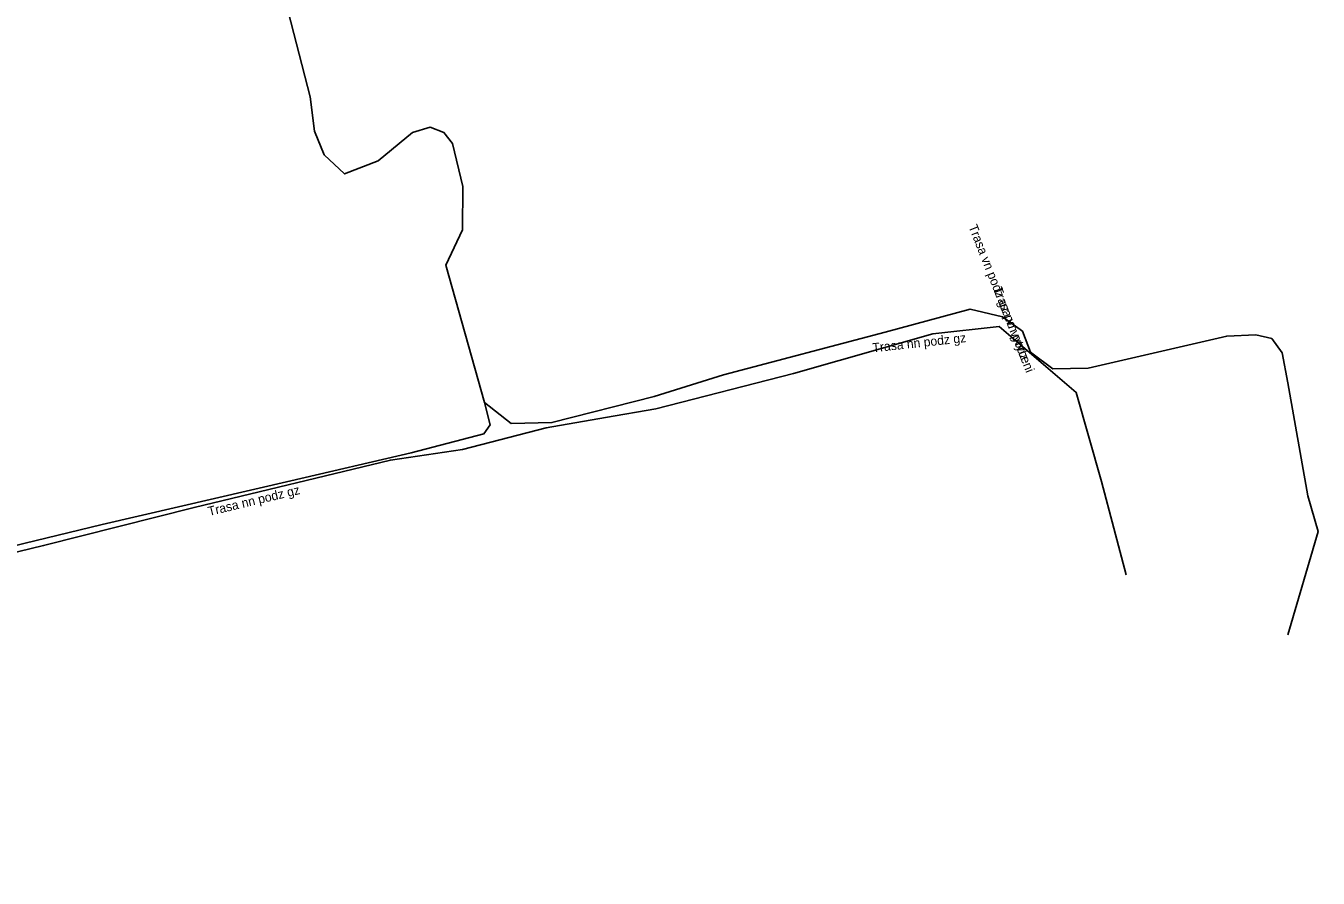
# Model space of a CAD drawing. Extents: x -473162 to -472629, y -1107202 to -1106680.
# Drawn here: x -472722.3 to -472651.3, y -1107100.6 to -1107053.9 of the extents above; entities that cross this region are included whole.
import ezdxf

# ---------------------------------------------------------------- set-up
doc = ezdxf.new("R2010")
doc.units = 0
for name, color, linetype in [('Popiskový text - Ostatní atributy Trasy', 7, 'Continuous'), ('Spojnice NN', 7, 'Continuous'), ('Spojnice VN', 7, 'Continuous')]:
    doc.layers.add(name, color=color, linetype=linetype)

msp = doc.modelspace()

# ---------------------------------------------------------------- linework, layer by layer
at = {"layer": 'Spojnice NN'}
for points in [[(-472661.88, -1107084), (-472663.22, -1107078.88), (-472664.62, -1107074), (-472668.85, -1107070.39), (-472672.48, -1107070.79), (-472680.13, -1107072.97), (-472687.68, -1107074.9), (-472690.449, -1107075.378)], [(-472690.449, -1107075.378), (-472693.7, -1107075.94), (-472698.29, -1107077.14), (-472702.25, -1107077.71), (-472713.02, -1107080.31), (-472721.28, -1107082.4), (-472726.565, -1107083.674)]]:
    msp.add_lwpolyline(points, dxfattribs=at)
at = {"layer": 'Spojnice VN'}
for points in [[(-472716.995, -1107015.385), (-472713.58, -1107028.195), (-472711.99, -1107034.185), (-472711.18, -1107037.515), (-472710.57, -1107041.2), (-472709.355, -1107047.29), (-472706.66, -1107057.79), (-472706.42, -1107059.68), (-472705.88, -1107060.975), (-472704.76, -1107062.02), (-472702.915, -1107061.3), (-472701.04, -1107059.755), (-472700.075, -1107059.45), (-472699.31, -1107059.75), (-472698.84, -1107060.35), (-472698.28, -1107062.705), (-472698.285, -1107065.095), (-472699.21, -1107067.025), (-472697.089, -1107074.548)], [(-472716.995, -1107015.385), (-472713.58, -1107028.195), (-472711.99, -1107034.185), (-472711.18, -1107037.515), (-472710.57, -1107041.2), (-472709.355, -1107047.29), (-472706.66, -1107057.79), (-472706.42, -1107059.68), (-472705.88, -1107060.975), (-472704.76, -1107062.02), (-472702.915, -1107061.3), (-472701.04, -1107059.755), (-472700.075, -1107059.45), (-472699.31, -1107059.75), (-472698.84, -1107060.35), (-472698.28, -1107062.705), (-472698.285, -1107065.095), (-472699.21, -1107067.025), (-472697.089, -1107074.548)], [(-472697.089, -1107074.548), (-472695.62, -1107075.7), (-472693.39, -1107075.66), (-472687.78, -1107074.22), (-472683.97, -1107073.04), (-472675.1, -1107070.7), (-472670.43, -1107069.44), (-472668.66, -1107069.85), (-472667.57, -1107070.65), (-472667.12, -1107071.79), (-472665.9, -1107072.71), (-472663.96, -1107072.67), (-472656.36, -1107070.91), (-472654.76, -1107070.84), (-472653.89, -1107071.05), (-472653.31, -1107071.84), (-472653.002, -1107073.475), (-472651.9, -1107079.67), (-472651.34, -1107081.63), (-472653.01, -1107087.293)], [(-472697.089, -1107074.548), (-472695.62, -1107075.7), (-472693.39, -1107075.66), (-472687.78, -1107074.22), (-472683.97, -1107073.04), (-472675.1, -1107070.7), (-472670.43, -1107069.44), (-472668.66, -1107069.85), (-472667.57, -1107070.65), (-472667.12, -1107071.79), (-472665.9, -1107072.71), (-472663.96, -1107072.67), (-472656.36, -1107070.91), (-472654.76, -1107070.84), (-472653.89, -1107071.05), (-472653.31, -1107071.84), (-472653.002, -1107073.475), (-472651.9, -1107079.67), (-472651.34, -1107081.63), (-472653.01, -1107087.293)], [(-472773.74, -1107100.64), (-472772.155, -1107097.49), (-472771.23, -1107094.96), (-472769.715, -1107093.61), (-472765.45, -1107092.705), (-472759.94, -1107091.32), (-472749.2, -1107088.65), (-472744.915, -1107087.62), (-472733.48, -1107084.87), (-472728.36, -1107083.805), (-472722.36, -1107082.295), (-472718.06, -1107081.25), (-472707.71, -1107078.845), (-472701.115, -1107077.315), (-472697.115, -1107076.27), (-472696.775, -1107075.78), (-472697.089, -1107074.548)], [(-472773.74, -1107100.64), (-472772.155, -1107097.49), (-472771.23, -1107094.96), (-472769.715, -1107093.61), (-472765.45, -1107092.705), (-472759.94, -1107091.32), (-472749.2, -1107088.65), (-472744.915, -1107087.62), (-472733.48, -1107084.87), (-472728.36, -1107083.805), (-472722.36, -1107082.295), (-472718.06, -1107081.25), (-472707.71, -1107078.845), (-472701.115, -1107077.315), (-472697.115, -1107076.27), (-472696.775, -1107075.78), (-472697.089, -1107074.548)]]:
    msp.add_lwpolyline(points, dxfattribs=at)

# ---------------------------------------------------------------- texts
at = {"layer": 'Popiskový text - Ostatní atributy Trasy'}
for s, rotation, p in [('Trasa vn podz gz po vytyceni', 291.54098, (-472670.534, -1107064.911)), ('Trasa vn podz', 291.54098, (-472669.181, -1107068.339)), ('Trasa nn podz gz', 6.28821, (-472675.77, -1107071.806)), ('Trasa nn podz gz', 13.57217, (-472712.197, -1107080.78))]:
    msp.add_text(s, height=0.5, rotation=rotation, dxfattribs=at).set_placement(p)

doc.saveas('drawing.dxf')
